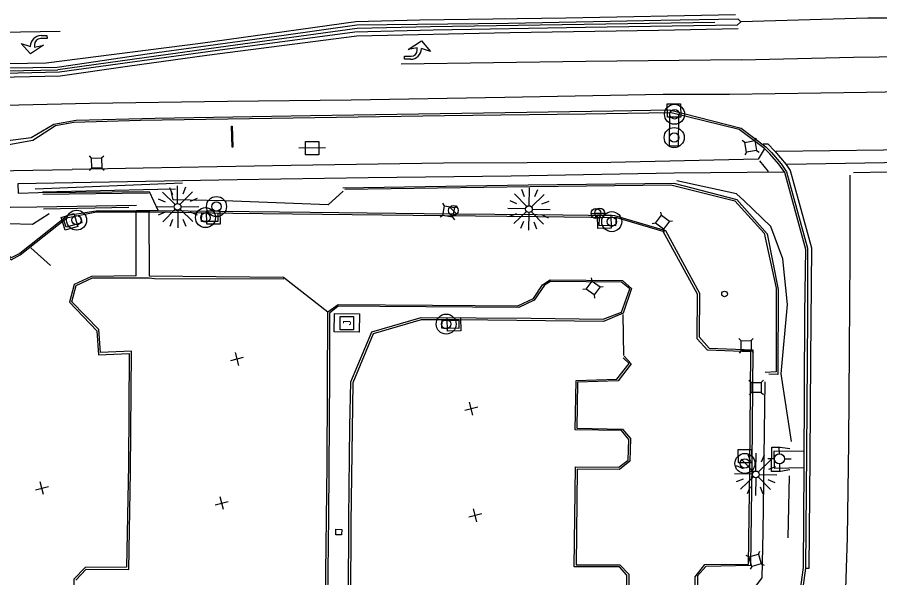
# Model space of a CAD drawing. Extents: x 4711259 to 4716401, y 890074 to 892728.
# Drawn here: x 4712263.3 to 4712586.5, y 891154.9 to 891365.1 of the extents above; entities that cross this region are included whole.
import ezdxf

# ---------------------------------------------------------------- set-up
doc = ezdxf.new("R2010")
doc.units = 0
for name, color, linetype in [('E_GT_WALL_Retaining', 7, 'Continuous'), ('E_HY_STORM_Inlet', 7, 'Continuous'), ('E_HY_STORM_MH', 7, 'Continuous'), ('E_RDWY_ROAD_Curb', 7, 'Continuous'), ('E_RDWY_ROAD_EdgeAsph', 7, 'Continuous'), ('E_RDWY_ROAD_EdgeConc', 7, 'Continuous'), ('E_RDWY_ROAD_Handrail', 7, 'Continuous'), ('E_RDWY_ROAD_Sidewalk', 7, 'Continuous'), ('E_RDWY_ROAD_Striping', 7, 'Continuous'), ('E_RDWY_ROAD_TBofCurb', 7, 'Continuous'), ('E_TERR_DTM_BrkLines', 7, 'Continuous'), ('E_TERR_DTM_RandomPt', 7, 'Continuous'), ('E_TRAF_ILLUM_Poles', 7, 'Continuous'), ('E_TRAF_PHOTOG_Signs', 7, 'Continuous'), ('E_UTIL_ELEC_GENERAL', 7, 'Continuous'), ('E_UTIL_ELEC_POLE', 7, 'Continuous'), ('E_UTIL_MISC_General', 7, 'Continuous'), ('E_UTIL_WTR_General', 7, 'Continuous')]:
    doc.layers.add(name, color=color, linetype=linetype)

msp = doc.modelspace()

# ---------------------------------------------------------------- linework, layer by layer
at = {"layer": 'E_GT_WALL_Retaining'}
for points in [[(4712385.33, 891301.16), (4712454.75, 891302.22), (4712509.27, 891302.92), (4712532.86, 891296.72), (4712544.23, 891283.93), (4712548.42, 891262.97), (4712548.33, 891231.15), (4712544.94, 891231.26)], [(4712322.55, 891300.63), (4712315.95, 891300.55), (4712272.68, 891299.46)], [(4712305.14, 891293.78), (4712273.14, 891293.17)], [(4712552.76, 891195.35), (4712549.22, 891194.77), (4712545.93, 891194.76), (4712546.05, 891203.95), (4712549.21, 891203.93), (4712552.79, 891203.45)]]:
    msp.add_lwpolyline(points, dxfattribs=at)
at = {"layer": 'E_HY_STORM_Inlet'}
for p, q in [((4712509.38, 891330.14), (4712509.38, 891330.14)), ((4712336.73, 891289.99), (4712336.73, 891289.99)), ((4712282.86, 891288.34), (4712282.86, 891288.34)), ((4712483.29, 891288.44), (4712483.29, 891288.44)), ((4712426.95, 891249.94), (4712426.95, 891249.94)), ((4712535.95, 891200.54), (4712535.95, 891200.54))]:
    msp.add_line(p, q, dxfattribs=at)
for points in [[(4712511.85, 891332.67), (4712511.91, 891327.67), (4712506.91, 891327.61), (4712506.85, 891332.61)], [(4712285.98, 891286.69), (4712281.2, 891285.22), (4712279.73, 891289.99), (4712284.51, 891291.47)], [(4712339.2, 891292.52), (4712339.26, 891287.52), (4712334.26, 891287.46), (4712334.2, 891292.46)], [(4712485.76, 891290.97), (4712485.82, 891285.97), (4712480.82, 891285.91), (4712480.76, 891290.91)], [(4712429.42, 891252.47), (4712429.48, 891247.47), (4712424.48, 891247.41), (4712424.42, 891252.41)], [(4712538.42, 891203.07), (4712538.48, 891198.07), (4712533.48, 891198.01), (4712533.42, 891203.01)]]:
    msp.add_lwpolyline(points, close=True, dxfattribs=at)
at = {"layer": 'E_HY_STORM_MH'}
for centre, radius in [((4712509.57, 891328.69), 3.75), ((4712509.57, 891328.69), 1.76), ((4712509.45, 891319.98), 3.75), ((4712509.45, 891319.98), 1.76), ((4712337.93, 891294.11), 3.75), ((4712333.82, 891289.95), 3.75), ((4712337.93, 891294.11), 1.76), ((4712285.53, 891289.01), 3.75), ((4712285.53, 891289.01), 1.76), ((4712333.82, 891289.95), 1.76), ((4712486.04, 891288.44), 3.75), ((4712486.04, 891288.44), 1.76), ((4712423.99, 891250.04), 3.75), ((4712423.99, 891250.04), 1.76), ((4712535.96, 891197.8), 3.75), ((4712535.96, 891197.8), 1.76)]:
    msp.add_circle(centre, radius, dxfattribs=at)
at = {"layer": 'E_RDWY_ROAD_Curb'}
for points in [[(4712278.26, 891346.38), (4712312.88, 891351.43), (4712363.13, 891358.38), (4712390.52, 891362.18), (4712447.4, 891362.89), (4712504.47, 891364.01), (4712533.33, 891364.49), (4712534.38, 891363.33)], [(4712534.38, 891363.33), (4712533.04, 891362.12), (4712476.18, 891361.22), (4712419.09, 891360.25), (4712389.78, 891359.45), (4712338.25, 891352.61), (4712279.05, 891344.47)], [(4712125.22, 891343.6), (4712174.9, 891344.81), (4712232.61, 891345.75), (4712278.26, 891346.38)], [(4712279.05, 891344.47), (4712232.18, 891343.4), (4712175.01, 891342.3), (4712125.26, 891341.45), (4712125.22, 891343.6)], [(4712285.33, 891326.48), (4712314.92, 891327.25), (4712373.15, 891328.3), (4712429.86, 891329.16), (4712486.57, 891329.95), (4712507.64, 891330.35), (4712534.48, 891323.48), (4712543.82, 891316.52), (4712545.87, 891314.33), (4712549.55, 891310.09), (4712551.57, 891307.18), (4712559.45, 891278.52), (4712559.34, 891253.31), (4712558.99, 891202.2), (4712558.66, 891158.48), (4712556.33, 891140.98)], [(4712257.86, 891318.58), (4712268.52, 891319.95), (4712277.02, 891325.05), (4712285.33, 891326.48)], [(4712256.06, 891291.47), (4712257.71, 891276.98), (4712261, 891274.15), (4712264.42, 891275.97), (4712281.77, 891289.75)], [(4712517.26, 891134.46), (4712517.26, 891155.26), (4712520.93, 891159.88), (4712537.28, 891160.01), (4712537.79, 891196.05), (4712538.18, 891239.58), (4712521.93, 891240.23), (4712518.03, 891244.53), (4712518.22, 891261.24), (4712505.32, 891284.81), (4712488, 891289.92), (4712458.38, 891290.3), (4712399.95, 891290.9), (4712344.06, 891291.52), (4712312.93, 891292), (4712292.98, 891291.94), (4712281.77, 891289.75)], [(4712307.81, 891268.08), (4712291.07, 891267.9), (4712284.59, 891264.94), (4712282.88, 891258.32), (4712293.03, 891247.45), (4712293.74, 891238.49), (4712305.19, 891239.03), (4712304.92, 891197.3), (4712304.2, 891158.94), (4712288.7, 891158.75), (4712284.49, 891154.35), (4712284.22, 891132.9), (4712287.03, 891129.28), (4712292.1, 891129.58), (4712294.06, 891133.16), (4712294.6, 891148.38), (4712321.96, 891148.36), (4712356.7, 891148.02), (4712356.74, 891132.39), (4712359.29, 891128.73), (4712363.92, 891128.74), (4712366.31, 891131.11)], [(4712312.73, 891268.11), (4712362.99, 891267.57)], [(4712379.68, 891254.65), (4712383.48, 891257.39), (4712418.93, 891257.11), (4712450.83, 891256.91), (4712456.72, 891259.58), (4712460.14, 891264.72), (4712462.93, 891266.6), (4712490.01, 891266.42), (4712493.4, 891263.39), (4712490.29, 891254.09)], [(4712490.72, 891238.06), (4712493.37, 891235.1), (4712488.42, 891228.78), (4712473.26, 891228.26), (4712473.02, 891210.99), (4712490.12, 891210.69), (4712493.09, 891207.19), (4712492.85, 891198.62), (4712488.91, 891195.55), (4712473.04, 891195.64), (4712472.72, 891159.79), (4712489.13, 891159.75), (4712492.42, 891156.27), (4712492.04, 891131.16), (4712489.3, 891127.62), (4712484.11, 891127.76), (4712481.67, 891130.84), (4712481.63, 891146.57), (4712450.51, 891147.13), (4712419.09, 891147.38), (4712418.95, 891131.21), (4712415.81, 891127.65)]]:
    msp.add_lwpolyline(points, dxfattribs=at)
at = {"layer": 'E_RDWY_ROAD_EdgeAsph'}
for points in [[(4712362.99, 891267.57), (4712379.68, 891254.65)], [(4712490.16, 891253.58), (4712490.43, 891238.26)]]:
    msp.add_lwpolyline(points, dxfattribs=at)
at = {"layer": 'E_RDWY_ROAD_EdgeConc'}
for points in [[(4712507.74, 891329.02), (4712507.58, 891317.02), (4712511.05, 891316.86), (4712511.16, 891328.32)], [(4712542.77, 891317.56), (4712544.51, 891317.66), (4712547.21, 891314.87), (4712551.43, 891309.85), (4712552.94, 891307.59), (4712560.91, 891278.63), (4712560.57, 891236.77), (4712560.31, 891200.04), (4712559.92, 891158.39), (4712558.84, 891158.38)], [(4712286.83, 891290.39), (4712287.41, 891288.06), (4712281.55, 891286.44), (4712280.89, 891288.64)], [(4712338.48, 891291.43), (4712338.49, 891288.54), (4712332.32, 891288.55), (4712332.41, 891291.5)], [(4712487.65, 891289.63), (4712487.51, 891286.84), (4712481.38, 891287.06), (4712481.44, 891289.87)], [(4712558.08, 891202.36), (4712546.84, 891202.26), (4712546.92, 891196.08), (4712557.88, 891196.32)]]:
    msp.add_lwpolyline(points, dxfattribs=at)
for points in [[(4712382.14, 891254.01), (4712391.5, 891253.87), (4712391.39, 891246.95), (4712382.03, 891247.1)], [(4712428.73, 891248.44), (4712422.41, 891248.55), (4712422.46, 891251.5), (4712428.78, 891251.39)]]:
    msp.add_lwpolyline(points, close=True, dxfattribs=at)
at = {"layer": 'E_RDWY_ROAD_Handrail'}
msp.add_lwpolyline([(4712272.81, 891298.78), (4712312.48, 891299.31)], dxfattribs=at)
at = {"layer": 'E_RDWY_ROAD_Sidewalk'}
for points in [[(4712543.16, 891315.67), (4712540.94, 891311.84), (4712485.72, 891310.68), (4712423.02, 891310.31), (4712365.96, 891309.45), (4712310.43, 891308.49), (4712283.8, 891307.95)], [(4712547.71, 891314.89), (4712587.86, 891315.33), (4712611.53, 891315.44)], [(4712607.78, 891310.71), (4712588.27, 891310.51), (4712551.65, 891309.83)], [(4712104.3, 891307.42), (4712106.24, 891304.5), (4712135.76, 891305.16), (4712190.09, 891306.56), (4712246.99, 891307.42), (4712283.8, 891307.95)], [(4712550.41, 891306.98), (4712509.4, 891306.6), (4712448.37, 891305.56), (4712394.71, 891304.89), (4712345.73, 891304.14), (4712284.13, 891303.06)], [(4712270.58, 891293.9), (4712260.8, 891293.75), (4712258.89, 891294.78), (4712258.42, 891302.64)], [(4712284.13, 891303.06), (4712263.44, 891302.63)], [(4712263.44, 891302.63), (4712263.55, 891299.16), (4712271.25, 891299.4)], [(4712271.25, 891299.4), (4712312.73, 891299.72), (4712315.91, 891292.78)], [(4712307.99, 891294.45), (4712270.58, 891293.9)], [(4712307.81, 891268.08), (4712307.89, 891291.75)], [(4712312.59, 891291.72), (4712312.73, 891268.11)]]:
    msp.add_lwpolyline(points, dxfattribs=at)
at = {"layer": 'E_RDWY_ROAD_Striping'}
for p, q in [((4712272.22, 891358.22), (4712274.41, 891358.25)), ((4712274.41, 891358.25), (4712274.42, 891357.11)), ((4712268.22, 891351.31), (4712264.7, 891355.21)), ((4712264.7, 891355.21), (4712268.18, 891354.17)), ((4712273.08, 891354.61), (4712268.22, 891351.31)), ((4712269.69, 891354.76), (4712269.7, 891353.9)), ((4712269.7, 891353.9), (4712273.08, 891354.61)), ((4712274.42, 891357.11), (4712271.95, 891357.08)), ((4712409.8, 891352.96), (4712414.69, 891356.22)), ((4712414.69, 891356.22), (4712418.18, 891352.29)), ((4712413.18, 891353.64), (4712409.8, 891352.96)), ((4712413.18, 891352.78), (4712413.18, 891353.64)), ((4712418.18, 891352.29), (4712414.7, 891353.36)), ((4712408.43, 891350.47), (4712410.91, 891350.48)), ((4712408.44, 891349.33), (4712408.43, 891350.47)), ((4712410.63, 891349.34), (4712408.44, 891349.33))]:
    msp.add_line(p, q, dxfattribs=at)
for points in [[(4712532.41, 891365.94), (4712468.79, 891364.75), (4712414.14, 891363.99), (4712390.14, 891363.4), (4712331.95, 891355.22), (4712274.12, 891347.88)], [(4712279.4, 891343.11), (4712304.56, 891346.7), (4712334.37, 891350.86), (4712390.58, 891358.05), (4712447.85, 891359.4), (4712503.62, 891360.29), (4712533.38, 891360.85)], [(4712279.39, 891359.77), (4712204.62, 891358.53), (4712147.05, 891357.5), (4712124.72, 891356.95)], [(4712274.12, 891347.88), (4712204.1, 891346.6), (4712149.06, 891345.49), (4712125.74, 891344.98)], [(4712534.67, 891349.09), (4712476.36, 891348.47), (4712407.12, 891347.43)], [(4712126.12, 891340.2), (4712179.08, 891341.02), (4712239.21, 891342.25), (4712279.4, 891343.11)], [(4712505.32, 891336.16), (4712446.04, 891334.99), (4712388.35, 891334.05), (4712342.02, 891333.49), (4712290.41, 891332.69)], [(4712290.41, 891332.69), (4712231.87, 891331.41), (4712174.54, 891330.39), (4712129.03, 891329.4)], [(4712572.14, 891095.18), (4712573.22, 891135.37), (4712574.44, 891170.05), (4712574.88, 891205.47), (4712575.19, 891240.43), (4712575.39, 891275.37), (4712575.43, 891305.84)], [(4712576.61, 891306.83), (4712601.89, 891307.32)], [(4712275.67, 891272.02), (4712268.38, 891278.61)]]:
    msp.add_lwpolyline(points, dxfattribs=at)
for centre, radius, start, end in [((4712272.27, 891354.13), 4.1, 90.7804, 179.4482), ((4712271.98, 891354.79), 2.29, 90.777, 180.7709), ((4712410.61, 891353.43), 4.1, 270.3097, 358.9775), ((4712410.9, 891352.77), 2.29, 270.3063, 0.3003)]:
    msp.add_arc(centre, radius, start, end, dxfattribs=at)
at = {"layer": 'E_RDWY_ROAD_TBofCurb'}
for points in [[(4712524.61, 891363.1), (4712475.73, 891362.31), (4712418.17, 891361.44), (4712390.7, 891360.83), (4712338.63, 891353.74), (4712278.44, 891345.37)], [(4712126.05, 891342.45), (4712135.63, 891342.44), (4712169.99, 891343.26), (4712233.43, 891344.44), (4712278.44, 891345.37)], [(4712284.51, 891325.69), (4712309.42, 891326.49), (4712366.6, 891327.38), (4712423.41, 891328.21), (4712476.26, 891328.89), (4712507.8, 891329.43)], [(4712538.08, 891159.49), (4712521.26, 891159.12), (4712518.23, 891155.62), (4712518.17, 891135.08), (4712529.2, 891127.19), (4712543.89, 891130.2), (4712555.48, 891141.41), (4712557.86, 891158.77), (4712558.16, 891196.42), (4712558.45, 891254.08), (4712558.73, 891277.96), (4712550.91, 891306.93), (4712548.62, 891309.95), (4712545.29, 891313.93), (4712543.28, 891315.85), (4712533.8, 891323.03), (4712507.8, 891329.43)], [(4712258.78, 891317.11), (4712269.1, 891319.03), (4712277.63, 891324.54), (4712284.51, 891325.69)], [(4712282.37, 891290.83), (4712264.25, 891276.49), (4712260.94, 891274.85), (4712258.22, 891277.5), (4712256.5, 891292.27)], [(4712282.37, 891290.83), (4712293.55, 891292.65), (4712304.76, 891292.55), (4712307.98, 891292.62), (4712312.53, 891292.67), (4712315.79, 891292.61), (4712372.99, 891291.95), (4712426.46, 891291.34), (4712457.97, 891291.08), (4712487.03, 891290.8), (4712506.2, 891285.11), (4712518.88, 891261.59), (4712518.76, 891245.2), (4712522.49, 891241.04), (4712538.95, 891240.4), (4712538.57, 891197.71), (4712538.08, 891159.49)], [(4712285.19, 891154.08), (4712289.09, 891158.13), (4712305.07, 891158.07), (4712305.65, 891194.76), (4712306.12, 891239.93), (4712294.46, 891239.33), (4712293.89, 891247.97), (4712283.71, 891258.41), (4712285.32, 891264.49), (4712291.45, 891267.32), (4712304.71, 891267.34), (4712307.76, 891267.33), (4712312.67, 891267.39), (4712314.73, 891267.18), (4712363.17, 891266.97)], [(4712489.67, 891254.5), (4712492.8, 891263.29), (4712489.64, 891265.78), (4712463.09, 891265.98), (4712460.88, 891264.62), (4712457.01, 891258.99), (4712451.2, 891256.31), (4712399.12, 891256.63), (4712383.58, 891256.76), (4712380.29, 891254.13)], [(4712380.29, 891254.13), (4712380.3, 891231.01), (4712379.84, 891177.84), (4712379.57, 891147.13), (4712380.88, 891143.55), (4712385.59, 891143.5), (4712387.35, 891147.06), (4712387.54, 891177.1), (4712387.92, 891211.62), (4712388.31, 891228.34), (4712396.2, 891247.13), (4712414.64, 891252.45), (4712455.81, 891252.27), (4712482.88, 891251.89)], [(4712482.88, 891251.89), (4712489.67, 891254.5)], [(4712410.66, 891129.12), (4712411.46, 891128.42), (4712415.44, 891128.34), (4712418.28, 891131.62), (4712418.42, 891148.18), (4712452.73, 891147.79), (4712482.33, 891147.55), (4712482.38, 891131.02), (4712484.34, 891128.39), (4712489.06, 891128.44), (4712491.4, 891131.26), (4712491.66, 891155.96), (4712488.95, 891159.09), (4712471.95, 891159.05), (4712472.45, 891196.52), (4712488.71, 891196.38), (4712492.18, 891199.01), (4712492.42, 891206.81), (4712489.75, 891210.13), (4712472.37, 891210.37), (4712472.67, 891228.87), (4712487.9, 891229.44), (4712492.56, 891235.31), (4712490.29, 891237.36)]]:
    msp.add_lwpolyline(points, dxfattribs=at)
at = {"layer": 'E_TERR_DTM_BrkLines'}
for points in [[(4712623.97, 891364.77), (4712582, 891364.75), (4712534.38, 891363.33)], [(4712534.67, 891349.09), (4712576.59, 891350.09), (4712624.53, 891350.79)], [(4712630.55, 891337.79), (4712581.52, 891336.86), (4712530.23, 891336.15), (4712505.32, 891336.16)], [(4712541.41, 891311.2), (4712544.62, 891307.27)], [(4712270, 891300.8), (4712325.22, 891302.94)], [(4712553.34, 891206.08), (4712549.5, 891231.45), (4712551.86, 891257.4), (4712550.17, 891274.46), (4712545.7, 891286.59), (4712535.71, 891296.24), (4712532.78, 891298.9), (4712510.38, 891303.73)], [(4712385.35, 891299.92), (4712379.78, 891294.69), (4712340.84, 891296.28), (4712321.7, 891296.64), (4712321.02, 891299.4)], [(4712386.06, 891300.64), (4712455.42, 891301.64), (4712508.15, 891302.23), (4712532.12, 891296.25), (4712543.19, 891284.16), (4712547.68, 891263.51), (4712547.61, 891232.16), (4712543.55, 891231.9)], [(4712275.18, 891291.42), (4712268.95, 891287.4), (4712259.85, 891287.58)], [(4712490.29, 891254.09), (4712483, 891251.01), (4712428.78, 891251.69), (4712414.63, 891251.58), (4712396.65, 891246.33), (4712389.08, 891228.06), (4712388.33, 891175.39), (4712388.18, 891146.82), (4712385.97, 891142.45), (4712380.76, 891142.52), (4712378.78, 891146.74), (4712379.38, 891197.22), (4712379.68, 891254.65)], [(4712543.44, 891228.39), (4712542.7, 891171.98), (4712542.34, 891154.9), (4712531.41, 891140.66)], [(4712552.09, 891169.91), (4712552.66, 891193.18)]]:
    msp.add_lwpolyline(points, dxfattribs=at)
at = {"layer": 'E_TERR_DTM_RandomPt'}
for p, q in [((4712346.31, 891234.55), (4712345.04, 891239.39)), ((4712343.26, 891236.33), (4712348.1, 891237.61)), ((4712430.99, 891217.73), (4712435.82, 891219)), ((4712434.04, 891215.95), (4712432.77, 891220.78)), ((4712273.14, 891186.09), (4712271.87, 891190.93)), ((4712270.09, 891187.87), (4712274.92, 891189.15)), ((4712337.49, 891182.28), (4712342.33, 891183.55)), ((4712340.54, 891180.49), (4712339.27, 891185.33)), ((4712435.53, 891175.96), (4712434.26, 891180.8)), ((4712432.48, 891177.75), (4712437.32, 891179.02))]:
    msp.add_line(p, q, dxfattribs=at)
at = {"layer": 'E_TRAF_ILLUM_Poles'}
for p, q in [((4712322.48, 891294.88), (4712317.71, 891299.53)), ((4712320.3, 891301.3), (4712321.41, 891298.67)), ((4712323.36, 891295.25), (4712323.28, 891301.92)), ((4712324.25, 891294.9), (4712328.9, 891299.67)), ((4712326.36, 891301.34), (4712325.29, 891298.7)), ((4712452.22, 891300.57), (4712453.23, 891297.9)), ((4712455.06, 891294.42), (4712455.21, 891301.08)), ((4712458.27, 891300.39), (4712457.11, 891297.79)), ((4712316.04, 891296.99), (4712318.68, 891295.91)), ((4712330.67, 891297.08), (4712328.04, 891295.97)), ((4712447.81, 891296.41), (4712450.41, 891295.24)), ((4712454.17, 891294.07), (4712449.57, 891298.89)), ((4712455.94, 891294.03), (4712460.76, 891298.63)), ((4712322.12, 891293.99), (4712315.46, 891293.91)), ((4712322.5, 891293.11), (4712317.85, 891288.34)), ((4712324.27, 891293.13), (4712329.04, 891288.47)), ((4712324.62, 891294.02), (4712331.29, 891294.1)), ((4712453.78, 891293.2), (4712447.12, 891293.35)), ((4712456.28, 891293.14), (4712462.95, 891292.99)), ((4712462.43, 891295.98), (4712459.77, 891294.97)), ((4712318.71, 891292.03), (4712316.08, 891290.93)), ((4712323.39, 891292.75), (4712323.47, 891286.09)), ((4712328.07, 891292.09), (4712330.71, 891291.02)), ((4712450.3, 891291.36), (4712447.63, 891290.35)), ((4712454.13, 891292.3), (4712449.31, 891287.7)), ((4712455, 891291.92), (4712454.85, 891285.25)), ((4712455.9, 891292.26), (4712460.5, 891287.44)), ((4712459.66, 891291.09), (4712462.26, 891289.93)), ((4712321.46, 891289.31), (4712320.39, 891286.67)), ((4712325.34, 891289.33), (4712326.45, 891286.71)), ((4712452.96, 891288.54), (4712451.79, 891285.94)), ((4712456.84, 891288.43), (4712457.85, 891285.77)), ((4712539.14, 891194.59), (4712534.52, 891199.4)), ((4712538.19, 891198.42), (4712537.17, 891201.08)), ((4712540.03, 891194.94), (4712540.16, 891201.6)), ((4712540.91, 891194.55), (4712545.71, 891199.17)), ((4712543.22, 891200.92), (4712542.07, 891198.32)), ((4712535.37, 891195.75), (4712532.77, 891196.91)), ((4712547.4, 891196.53), (4712544.73, 891195.51)), ((4712538.76, 891193.71), (4712532.09, 891193.85)), ((4712539.1, 891192.82), (4712534.3, 891188.2)), ((4712540.87, 891192.79), (4712545.49, 891187.98)), ((4712541.25, 891193.66), (4712547.92, 891193.53)), ((4712535.28, 891191.87), (4712532.61, 891190.85)), ((4712539.98, 891192.44), (4712539.85, 891185.77)), ((4712547.24, 891190.47), (4712544.64, 891191.63)), ((4712537.94, 891189.06), (4712536.79, 891186.46)), ((4712542.84, 891186.3), (4712541.82, 891188.96))]:
    msp.add_line(p, q, dxfattribs=at)
for centre in [(4712323.37, 891294), (4712455.03, 891293.17), (4712540.01, 891193.69)]:
    msp.add_circle(centre, 1.25, dxfattribs=at)
at = {"layer": 'E_TRAF_PHOTOG_Signs'}
msp.add_lwpolyline([(4712343.85, 891316.35), (4712343.54, 891324.21), (4712343.79, 891324.22), (4712344.11, 891316.36)], close=True, dxfattribs=at)
at = {"layer": 'E_UTIL_ELEC_GENERAL'}
msp.add_lwpolyline([(4712389.23, 891252.9), (4712389.3, 891247.9), (4712384.3, 891247.84), (4712384.23, 891252.84)], close=True, dxfattribs=at)
at = {"layer": 'E_UTIL_ELEC_POLE'}
msp.add_line((4712378.77, 891316.08), (4712368.77, 891315.96), dxfattribs=at)
msp.add_lwpolyline([(4712376.3, 891313.55), (4712371.3, 891313.49), (4712371.24, 891318.49), (4712376.24, 891318.55)], close=True, dxfattribs=at)
at = {"layer": 'E_UTIL_MISC_General'}
msp.add_lwpolyline([(4712384.84, 891173.06), (4712384.8, 891170.97), (4712382.63, 891171.02), (4712382.68, 891173.11)], close=True, dxfattribs=at)
msp.add_circle((4712528.32, 891261.34), 1.05, dxfattribs=at)
at = {"layer": 'E_UTIL_WTR_General'}
for p, q in [((4712535.94, 891318.16), (4712534.97, 891318.84)), ((4712539.63, 891318.83), (4712540.3, 891319.79)), ((4712291.14, 891312.26), (4712290.3, 891313.08)), ((4712294.89, 891312.31), (4712295.71, 891313.15)), ((4712536.6, 891314.47), (4712535.93, 891313.51)), ((4712540.29, 891315.13), (4712541.26, 891314.46)), ((4712291.19, 891308.51), (4712290.36, 891307.67)), ((4712294.94, 891308.56), (4712295.78, 891307.73)), ((4712423.42, 891294.43), (4712422.75, 891295.4)), ((4712425.34, 891293.92), (4712428.03, 891291.3)), ((4712427.11, 891293.76), (4712428.08, 891294.43)), ((4712422.74, 891290.75), (4712421.77, 891290.08)), ((4712426.43, 891290.07), (4712427.1, 891289.1)), ((4712478.27, 891291.48), (4712482.02, 891291.52)), ((4712479.67, 891291.61), (4712483.42, 891291.66)), ((4712504.63, 891290.86), (4712504.45, 891292.02)), ((4712502.4, 891287.84), (4712501.23, 891287.67)), ((4712507.64, 891288.63), (4712508.81, 891288.8)), ((4712505.41, 891285.61), (4712505.59, 891284.45)), ((4712478.66, 891266.19), (4712478.49, 891267.36)), ((4712481.68, 891263.96), (4712482.84, 891264.14)), ((4712476.43, 891263.18), (4712475.27, 891263)), ((4712479.45, 891260.95), (4712479.62, 891259.78)), ((4712534.51, 891243.79), (4712533.67, 891244.61)), ((4712538.26, 891243.84), (4712539.08, 891244.68)), ((4712534.55, 891240.04), (4712533.73, 891239.2)), ((4712538.3, 891240.09), (4712539.15, 891239.26)), ((4712538.28, 891228.12), (4712537.44, 891228.94)), ((4712542.03, 891228.16), (4712542.85, 891229.01)), ((4712538.32, 891224.37), (4712537.5, 891223.52)), ((4712542.07, 891224.41), (4712542.92, 891223.59)), ((4712548.86, 891201.39), (4712548.83, 891203.89)), ((4712547.01, 891199.5), (4712544.51, 891199.47)), ((4712550.76, 891199.54), (4712553.26, 891199.57)), ((4712548.91, 891197.64), (4712548.94, 891195.14)), ((4712541.03, 891163.81), (4712541.59, 891164.85)), ((4712537.43, 891162.76), (4712536.4, 891163.32)), ((4712538.49, 891159.16), (4712537.92, 891158.12)), ((4712542.08, 891160.21), (4712543.12, 891159.65))]:
    msp.add_line(p, q, dxfattribs=at)
for points in [[(4712536.6, 891314.47), (4712535.94, 891318.16), (4712539.63, 891318.83), (4712540.29, 891315.13)], [(4712294.94, 891308.56), (4712291.19, 891308.51), (4712291.14, 891312.26), (4712294.89, 891312.31)], [(4712422.74, 891290.75), (4712423.42, 891294.43), (4712427.11, 891293.76), (4712426.43, 891290.07)], [(4712504.63, 891290.86), (4712507.64, 891288.63), (4712505.41, 891285.61), (4712502.4, 891287.84)], [(4712478.66, 891266.19), (4712481.68, 891263.96), (4712479.45, 891260.95), (4712476.43, 891263.18)], [(4712534.51, 891243.79), (4712538.26, 891243.84), (4712538.3, 891240.09), (4712534.55, 891240.04)], [(4712538.28, 891228.12), (4712542.03, 891228.16), (4712542.07, 891224.41), (4712538.32, 891224.37)], [(4712541.03, 891163.81), (4712542.08, 891160.21), (4712538.49, 891159.16), (4712537.43, 891162.76)]]:
    msp.add_lwpolyline(points, close=True, dxfattribs=at)
for centre in [(4712426.68, 891292.61), (4712480.14, 891291.5), (4712481.54, 891291.63), (4712548.89, 891199.52)]:
    msp.add_circle(centre, 1.87, dxfattribs=at)

# ---------------------------------------------------------------- texts
at = {"layer": 'E_UTIL_ELEC_GENERAL'}
msp.add_text('J', height=3, rotation=90.6931, dxfattribs=at).set_placement((4712388.34, 891249.54))

doc.saveas('drawing.dxf')
